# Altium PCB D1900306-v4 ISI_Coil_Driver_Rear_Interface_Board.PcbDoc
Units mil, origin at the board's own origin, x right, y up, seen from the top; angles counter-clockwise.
Board outline 14000 x 2000 mil, 6 copper layers (Top Layer, MidLayer1, InternalPlane1, InternalPlane2, InternalPlane3, Bottom Layer), stack 92.2 mil thick; 51 components, 49 nets, 219 pads, 22 vias.
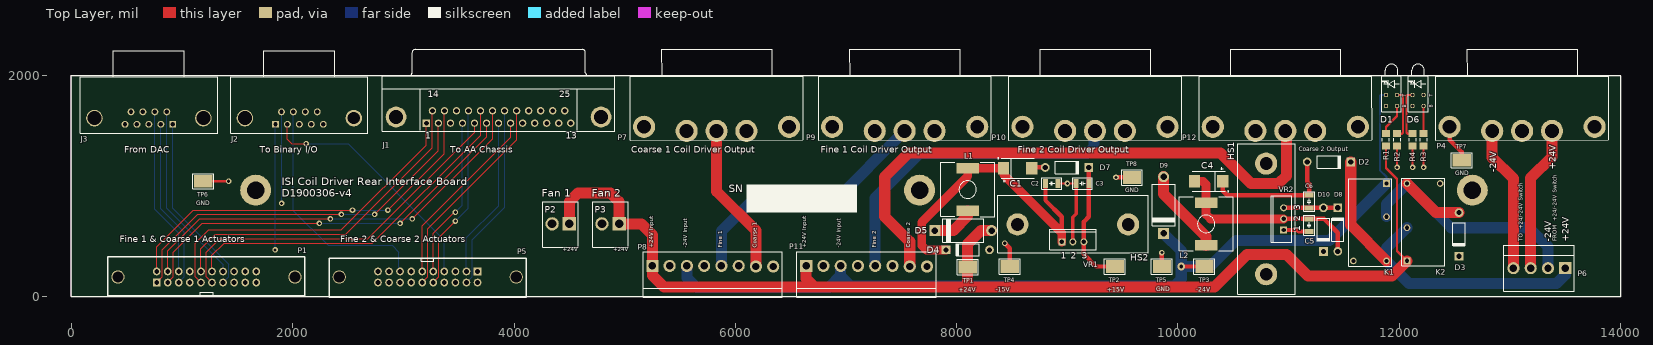
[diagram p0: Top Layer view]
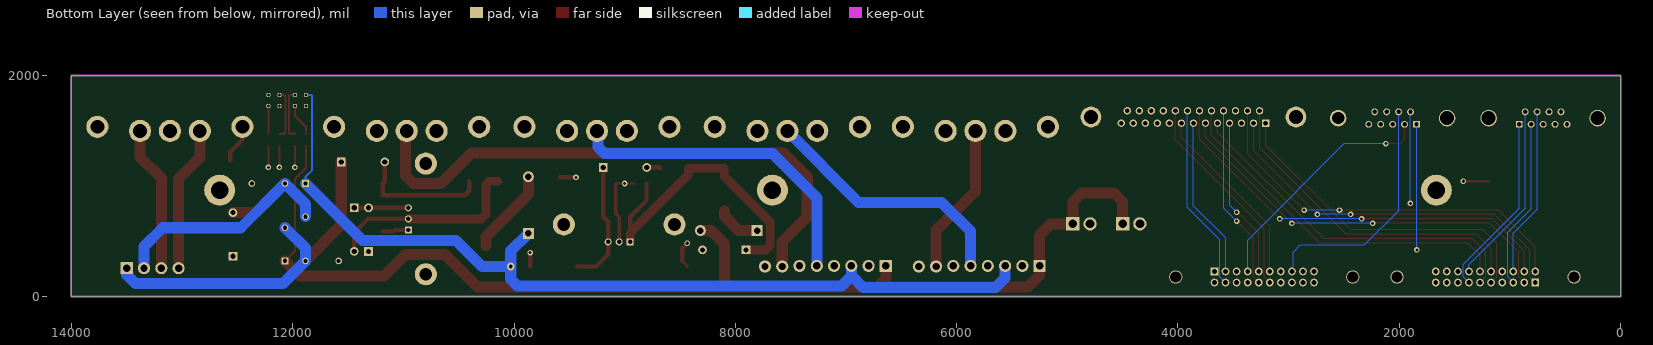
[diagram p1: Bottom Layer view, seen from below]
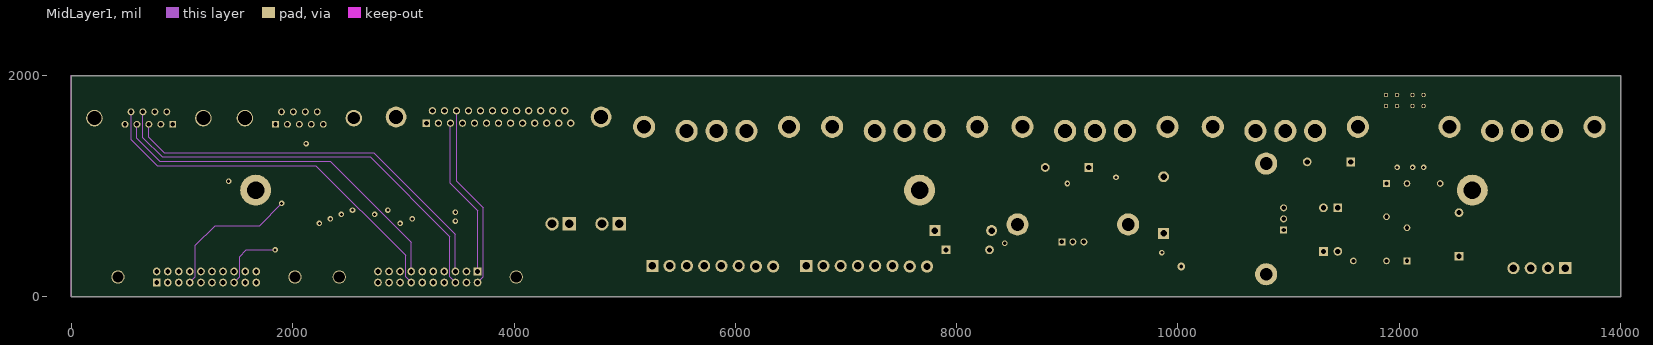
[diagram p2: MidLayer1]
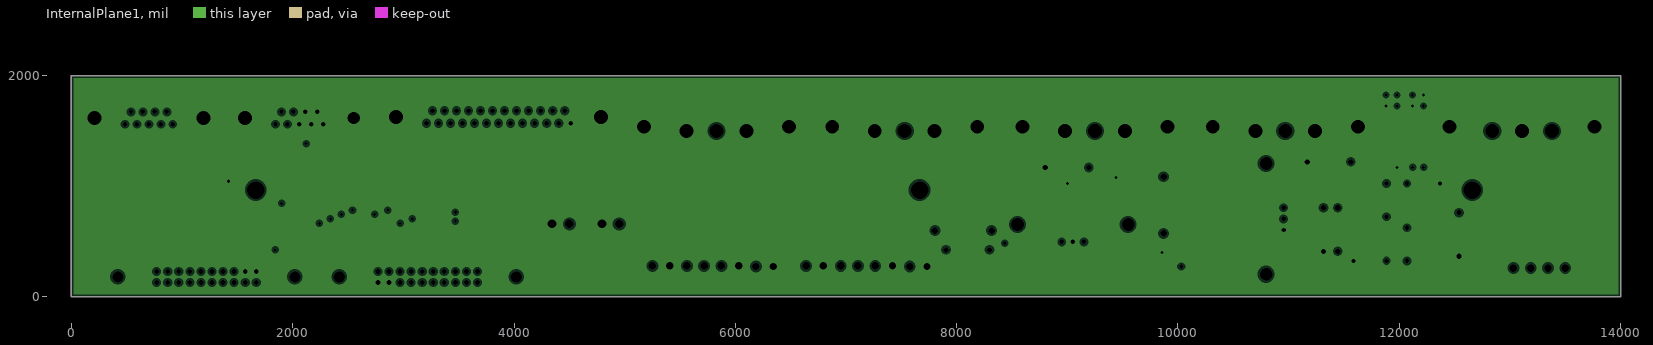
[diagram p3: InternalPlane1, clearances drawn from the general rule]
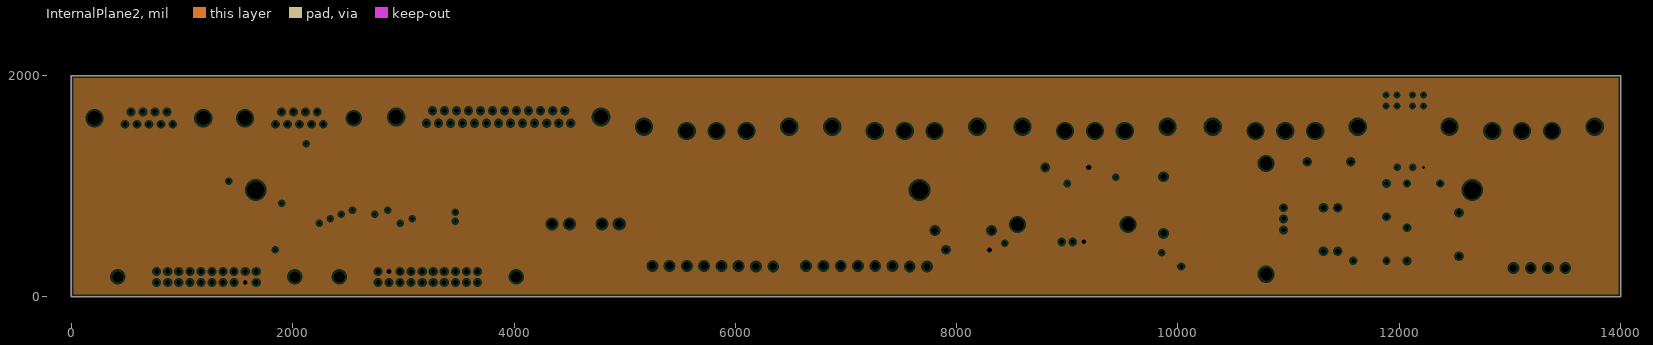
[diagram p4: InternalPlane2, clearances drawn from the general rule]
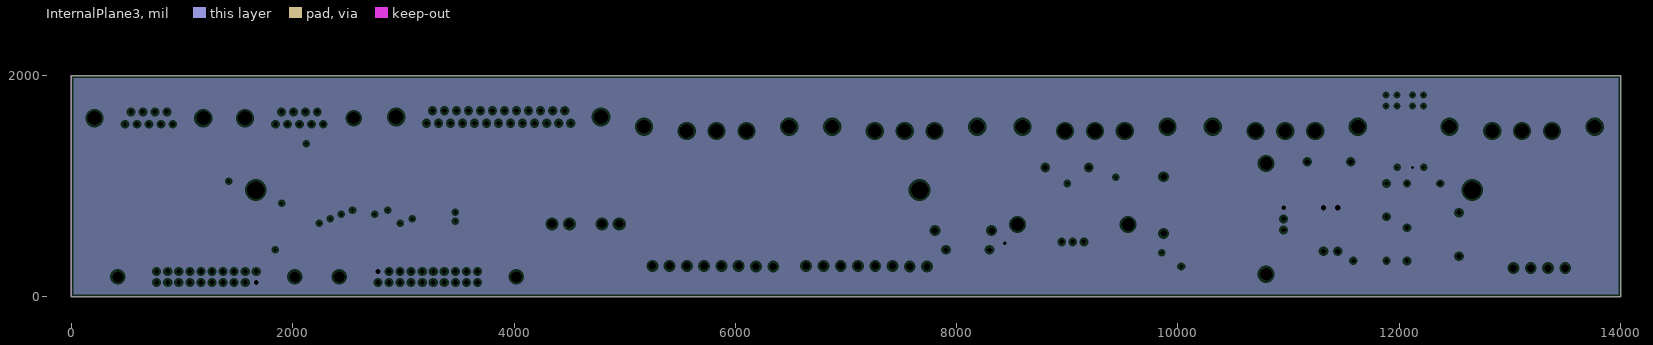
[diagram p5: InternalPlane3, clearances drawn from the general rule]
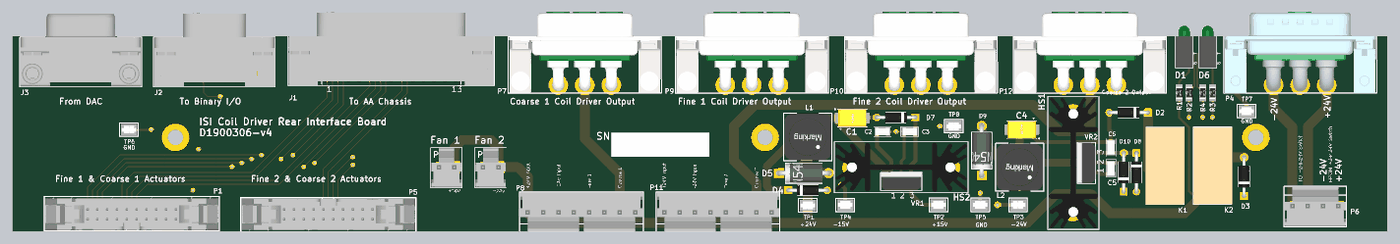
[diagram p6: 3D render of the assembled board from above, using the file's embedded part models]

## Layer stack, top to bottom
Top Solder: solder mask 0.4, Solder Resist, Dk 3.5
Top Layer: signal copper 1.4
Dielectric1: prepreg 9.7, FR-4, Dk 4.2
MidLayer1: signal copper 1.4
Dielectric2: core 27.35, FR-4, Dk 4.2
InternalPlane1: plane copper 1.4, net GND
Dielectric3: prepreg 9.7, FR-4, Dk 4.2
InternalPlane2: plane copper 1.4, net +15
Dielectric4: core 27.35, FR-4, Dk 4.2
InternalPlane3: plane copper 1.4, net -15
Dielectric5: prepreg 9.7, FR-4, Dk 4.2
Bottom Layer: signal copper 1.4
Bottom Solder: solder mask 0.4, Solder Resist, Dk 3.5

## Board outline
0,-5 0,1995 1700,1995 14000,1995 14000,-5 0,-5

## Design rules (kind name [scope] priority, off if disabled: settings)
Clearance [All] p1: gap=10 ignorepadtopadclearanceinfootprint=FALSE except(0: Arc-Hole Track-Hole SMDPad-Hole THPad-Hole Via-Hole Fill-Hole Poly-Hole Region-Hole Text-Hole)
FabricationTestPointUsage TestPointUsage [All] p1: valid=0 allowmultiple=FALSE
FabricationTestpoint Testpoint [All] p1: side=3 testpointundercomponent=TRUE minsize=40 maxsize=100 preferedsize=60 minholesize=0 maxholesize=40 preferedholesize=32 testpointgrid=1 allowsidetop=TRUE allowsidebottom=TRUE usegrid=TRUE gridtolerance=0.01
Height [All] p1: minheight=0 maxheight=4000 prefheight=2000
HoleSize [All] p1: absolutevalues=TRUE maxlimit=300 minlimit=1 maxpercent=80.000 minpercent=20.000
PlaneClearance [All] p1: clearance=20
PlaneConnect [All] p1: planeconnectstyle=Relief reliefexpansion=30 reliefentries=4 reliefconductorwidth=30 reliefairgap=20
PolygonConnect [All] p1: connectstyle=Relief reliefconductorwidth=10 reliefentries=4 polygonreliefangle="90 Angle" airgapwidth=10
RoomDefinition "D1900306-v4 ISI_Coil_Driver_Rear_Interface_Board" [InComponentClass('D1900306-v4 ISI_Coil_Driver_Rear_Interface_Board')] p1: confinementstyle=ConfineIn formatcopy=TRUE lockcomponents=FALSE outline 65,-25 13905,-25 13905,2255 65,2255
RoutingVias [All] p1: holewidth=28 width=50 viastyle="Through Hole" minholewidth=28 minwidth=50 maxholewidth=128 maxwidth=150
SolderMaskExpansion [All] p1: expansion=4 istentingtop=FALSE
Width [All] p1: maxlimit=200 minlimit=5 preferedwidth=20
24 further rules are at their usual default settings.

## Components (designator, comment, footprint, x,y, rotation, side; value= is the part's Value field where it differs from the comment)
C1 "33uF, 50V" T543x 8551.77,1157.91 r180 top
C2 "1uF" "1206 (3216 METRIC) CAP" 8860,1020 r180 top
C3 "0.1uF 50V" "1206 (3216 METRIC) CAP" 9137.09,1020 r180 top
C4 "33uF, 50V" T543x 10277.74,1040 r0 top
C5 "1uF" "1206 (3216 METRIC) CAP" 11185,642.91 r90 top
C6 "0.1uF 50V" "1206 (3216 METRIC) CAP" 11185,857.09 r90 top
D1 "Stacked LED" DUAL_LED 11840,1995 r90 top
D2 "1N4001" DO-41 11365,1215 r0 top
D3 "1N4001" DO-41 12540,560 r270 top
D4 "1N4001" DO-41 8100,420 r180 top
D5 "1N5404" DO-201AD 8060,595 r180 top
D6 "Stacked LED" DUAL_LED 12080,1995 r90 top
D7 "1N4001" DO-41 8997.32,1165 r0 top
D8 "1N4001" DO-41 11445,603.15 r90 top
D9 "1N5404" DO-201AD 9870,825 r270 top
D10 "1N4001" DO-41 11315,603.15 r270 top
HS1 "Heat Sink" "HEAT SINK TO-220" 10797,700 r90 top
HS2 "Heat Sink" "HEAT SINK TO-220" 9050,650 r180 top
J1 "D Connector 25" DSUB1.385-2H25A 3860,1995 r0 top
J2 "D9F 90deg" DB9/F/RA 2060,1555 r0 top
J3 "D9M 90deg" DB9/M/RA 700,1555 r0 top
K1 "Relay-SPST" "PANASONIC RELAY_5A" 11885,1020 r90 top
K2 "Relay-SPST" "PANASONIC RELAY_5A" 12070,320 r270 top
L1 "1.43 uH, 12A, choke" "POWER CHOKE" 8100,965 r0 top
L2 "1.43 uH, 12A, choke" "POWER CHOKE" 10255,655 r0 top
P1 "Header 20" "IDC 20 _VERTICAL" 1220,175 r0 top
P2 "Molex 2 PIN" MOLE_2PIN_0.156 4500,655 r270 top
P3 "Molex 2 PIN" MOLE_2PIN_0.156 4950,655 r270 top
P4 "Conec-3 (MFM)" "CONEC-3 - (+/-24V M/F/M) PWR IN (10.7MM TAB)" 13380,1495 r90 top
P5 "Header 20" "IDC 20 _VERTICAL" 3220,175 r180 top
P6 "Header 4" "4 PIN_MOLEX" 13500,255 r0 top
P7 "Conec-3 (F)" "CONEC-3 - (FFF) PWR OUT (10.7MM TABS)" 6100,1495 r90 top
P8 "8 Pin Molex (0.156\")" "8 PIN_MOLEX(0.156)" 5250,275 r180 top
P9 "Conec-3 (F)" "CONEC-3 - (FFF) PWR OUT (10.7MM TABS)" 7800,1495 r90 top
P10 "Conec-3 (F)" "CONEC-3 - (FFF) PWR OUT (10.7MM TABS)" 9520,1495 r90 top
P11 "8 Pin Molex (0.156\")" "8 PIN_MOLEX(0.156)" 6640,275 r180 top
P12 "Conec-3 (F)" "CONEC-3 - (FFF) PWR OUT (10.7MM TABS)" 11240,1495 r90 top
R1 "1K" 3216[1206] 11880,1415 r90 top
R2 "1K" 3216[1206] 11980,1414.88 r90 top
R3 "1K" 3216[1206] 12220,1415 r90 top
R4 "1K" 3216[1206] 12120,1415 r90 top
TP1 "SMT TP" SMT_TP 8100,265 r90 top
TP2 "SMT TP" SMT_TP 9430,270 r90 top
TP3 "SMT TP" SMT_TP 10240,270 r90 top
TP4 "SMT TP" SMT_TP 8480,270 r270 top
TP5 "SMT TP" SMT_TP 9855,270 r90 top
TP6 "SMT TP" SMT_TP 1192,1040 r90 top
TP7 "SMT TP" SMT_TP 12565,1230 r90 top
TP8 "SMT TP" SMT_TP 9585,1075 r90 top
VR1 "LM340T" TO-220AB 9050,492 r0 top
VR2 "LM7915CT" TO-220AB 10955,700 r90 top

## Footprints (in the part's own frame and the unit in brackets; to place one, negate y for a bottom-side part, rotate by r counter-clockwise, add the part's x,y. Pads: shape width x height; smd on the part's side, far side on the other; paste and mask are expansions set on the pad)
"4 PIN_MOLEX" [mil]
  rect 110x110 hole 67: 1(0,0)
  round 110 hole 67: 2(-156,0) 3(-312,0) 4(-468,0)
  silkscreen extent -554,-210 81,205, body extent -544,-199 74,195, height 581
"8 PIN_MOLEX(0.156)" [mil]
  rect 110x110 hole 67: 1(0,0)
  round 110 hole 67: 2(-156,0) 3(-312,0) 4(-468,0) 5(-624,0) 6(-780,0) 7(-936,5) 8(-1092,5)
  silkscreen extent -1176,-128 84,282, body extent -1167,-121 75,273, height 581
"1206 (3216 METRIC) CAP" [mm] "Chip Capacitor; Body 3.2 x 1.6 mm (LxW typ)"
  rect 1.15x2.1 smd: 1(-1.45,0) 2(1.45,0)
  silkscreen extent -2.29,-1.27 2.29,1.27, body extent -1.8,-0.93 1.8,0.97, height 1.11
3216[1206] [mm] "Chip Resistor; Body 3.2 x 1.6 mm (LxW typ)"
  rect 1.6x1.8 smd: 1(-1.4,0) 2(1.4,0)
  silkscreen extent -0.3,-0.8 0.3,0.8, body extent -1.6,-0.8 1.6,0.8, height 0.55
"CONEC-3 - (+/-24V M/F/M) PWR IN (10.7MM TAB)" [mil] "303W3CPXX56K40X"
  round 200 hole 125: 1(0,0) 2(0,270) 3(0,540) 4(37.4,925) 5(37.4,-386)
  silkscreen extent -83,-510 736,1048, body extent -87,-502 748,1042, height 544
"CONEC-3 - (FFF) PWR OUT (10.7MM TABS)" [mil] "3003W3SXX56K40X"
  round 200 hole 125: 1(0,0) 2(0,270) 3(0,540) 4(37.4,925) 5(37.4,-386)
  silkscreen extent -83,-510 736,1048, body extent -79,-502 748,1042, height 499
DB9/F/RA [mil] "Amphenol part# 617-C009S-AJ120"
  rect 62x62 hole 40: 1(-216,0)
  round 62 hole 40: 2(-108,0) 3(0,0) 4(108,0) 5(216,0) 6(-162,112) 7(-54,112) 8(54,112) 9(162,112)
  round 150 hole 126: 10(-492,56)
  round 150 hole 110: 11(492,56)
  silkscreen extent -620,-80 620,666, body extent -610,-70 610,674, height 495
DB9/M/RA [mil] "Amphenol Part# 617-C009P-AJ120"
  rect 62x62 hole 40: 1(216,0)
  round 62 hole 40: 2(108,0) 3(0,0) 4(-108,0) 5(-216,0) 6(162,112) 7(54,112) 8(-54,112) 9(-162,112)
  round 150 hole 126: 10(492,56) 11(-492,56)
  silkscreen extent -620,-80 620,666, body extent -611,-70 611,662, height 495
DO-41 [mm] "Diode, Axial; Body 5.2 x 2.7 mm (LxDia. max), Lead Dia. 0.86 mm (max)"
  round 2 hole 1.2: 1(-5,0)
  rect 2x2 hole 1.2: 2(5,0)
  silkscreen extent -2.65,-1.42 2.75,1.4, body extent -5.4,-1.36 5.46,1.36, height 2.86
DO-201AD [mm] "Diode Standard 400V 3A Through Hole DO-201AD"
  round 2.5 hole 1.5: 1(-6.5,0)
  rect 2.5x2.5 hole 1.5: 2(6.5,0)
  silkscreen extent -4.75,-2.65 4.75,2.65, body extent -6.95,-2.58 6.95,2.45, height 5.51
DSUB1.385-2H25A [mm] "Connector; D Subminiature; 25 Position; Right Angle; Pitch 1.385 mm"
  rect 1.69x1.69 hole 1.09: 1(-16.566,-10.92)
  round 1.69 hole 1.09: 2(-13.805,-10.92) 3(-11.044,-10.92) 4(-8.283,-10.92) 5(-5.522,-10.92) 6(-2.761,-10.92) 7(0,-10.92) 8(2.761,-10.92) 9(5.522,-10.92) 10(8.283,-10.92) 11(11.044,-10.92) 12(13.805,-10.92) 13(16.566,-10.92) 14(-15.185,-8.08) 15(-12.425,-8.08) 16(-9.663,-8.08) 17(-6.903,-8.08) 18(-4.142,-8.08) 19(-1.38,-8.08) 20(1.38,-8.08) 21(4.142,-8.08) 22(6.903,-8.08) 23(9.663,-8.08) 24(12.425,-8.08) 25(15.185,-8.08)
  round 4.76 hole 3.26: 26(-23.526,-9.5) 27(23.526,-9.5)
  silkscreen extent -26.67,-12.83 26.67,6, body extent -26.54,-12.7 26.54,6.25, height 12.56
DUAL_LED [mil] "Stacked LED GREEN, Digi Key Part # 67-1321-ND"
  round 40 hole 25: 1(-175,-140) 2(-175,-40) 3(-275,-140) 4(-275,-40)
  silkscreen extent -325,-180 104,0, body extent -320,-175 104,-5, height 380
"HEAT SINK TO-220" [mil]
  round 200 hole 115: 1(-500,0) 2(500,0)
  silkscreen extent -680,-265 680,255, body extent -670,-257 670,247, height 2005
"IDC 20 _VERTICAL" [mil]
  round 120 hole 100: 0(-800,0) 0(800,0)
  rect 70x70 hole 43: 1(-450,-50)
  round 70 hole 43: 2(-450,50) 3(-350,-50) 4(-350,50) 5(-250,-50) 6(-250,50) 7(-150,-50) 8(-150,50) 9(-50,-50) 10(-50,50) 11(50,-50) 12(50,50) 13(150,-50) 14(150,50) 15(250,-50) 16(250,50) 17(350,-50) 18(350,50) 19(450,-50) 20(450,50)
  silkscreen extent -891,-170 890,182, body extent -881,-159 879,172, height 1044
MOLE_2PIN_0.156 [mil]
  rect 120x120 hole 79: 1(0,0)
  round 120 hole 79: 2(0,-156)
  silkscreen extent -200,-240 210,80, body extent -193,-231 201,75, height 581
"PANASONIC RELAY_5A" [mil]
  rect 60x60 hole 40: 1(0,0)
  round 60 hole 40: 2(-300,0)
  round 60 hole 36: 3(-700,0) 4(-700,300)
  silkscreen extent -746,-47 44,343, body extent -744,-47 43,347, height 630
"POWER CHOKE" [mm] "PCD1572-ND"
  rect 5.2x2.4 smd: 1(0,-4.9) 2(0,4.9)
  silkscreen extent -6.22,-6.2 6.22,6.22, body extent -6,-6 6,6, height 9.46
SMT_TP [mil] "Surface Mount Test Point"
  rect 115x165 smd: 1(0,0)
  silkscreen extent -69,-94 70,95, body extent -40,-75 40,75, height 91
T543x [mm]
  rect 2.55x2.77 smd: 1(3.22,0) 2(-3.22,0)
  silkscreen extent -3.8,-2.42 4.57,3.18, body extent -3.8,-2.31 3.8,2.29, height 4.31
TO-220AB [mm] "TO, Thru-Hole, Vertical, Heatsink Mounted; 3 In-Line Leads; Pitch 2.54 mm"
  rect 1.6x1.6 hole 1: 1(-2.54,0)
  round 1.6 hole 1: 2(0,0) 3(2.54,0)
  silkscreen extent -5.35,-1.85 5.35,2.85, body extent -5.27,-1.84 5.27,2.86, height 22.56

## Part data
C1 C4: library part T543X, "33µF Molded Tantalum Polymer Capacitor 50V 2917 (7343 Metric) 40mOhm @ 100kHz", Capacitance=33uF, Case/Package=Molded, Case Code (Imperial)=2917, Case Code (Metric)=7343, Dielectric Material=Tantalum, ESR (Equivalent Series Resistance)=40mR, Leakage Current=165uA, Manufacturer=KEMET, Manufacturer Part Number=T543X336M050AHE040, Max Operating Temperature=105°C, Min Operating Temperature=-55°C, Package Quantity=500, Supplier Part Number 1=399-8854-1-ND, Tolerance=20%, Voltage=50V
C2 C5: library part CAP, "1µF ±10% 25V Ceramic Capacitor X7R 1206 (3216 Metric)", Case/Package=1206, Dielectric=X7R, Dielectric Material=Ceramic, Manufacturer=TDK-Lambda, Manufacturer Part Number=C1206C105K3RACTU, Supplier Part Number 1=399-1255-1-ND, Tolerance=10%, Voltage Rating (DC)=25V
C3 C6: "0.1µF ±5% 50V Ceramic Capacitor X7R 1206 (3216 Metric)", Capacitance=100nF, Case/Package=1206, Case Code (Metric)=3216, Dielectric=X7R, Dielectric Material=Ceramic, Manufacturer=KEMET, Manufacturer Part Number=C1206C104J5RACTU, Max Operating Temperature=125°C, Min Operating Temperature=-55°C, Package Quantity=1, Supplier Part Number 1=399-1250-1-ND, Tolerance=5%, Voltage=50V
D1 D6: library part "Dual Stacked LED", "Dual Green LED", Color=Green, Forward Current=25mA, Forward Voltage=2.2V, Manufacturer=Lumex, Manufacturer Part Number=SSF-LXH240GGD, Package Quantity=1000, Supplier Part Number 1=67-1321-ND
D2 D3 D4 D7 D8 D10: library part "Diode 1N4001", "1 Amp General Purpose Rectifier", Average Rectified Current=1A, Capacitance=8pF, Forward Voltage=1V, Manufacturer=Diodes, Manufacturer Part Number=1N4001G-T, Max Operating Temperature=175°C, Max Repetitive Reverse Voltage (Vrrm)=50V, Max Surge Current=30A, Min Operating Temperature=-65°C, Package Quantity=5000, Peak Reverse Current=5uA, Supplier Part Number 1=1N4001GDICT-ND
D5 D9: library part "Diode 1N5404", "Diode Standard 400V 3A Through Hole DO-201AD", Average Rectified Current=3A, Capacitance=30pF, Forward Voltage=1.2V, Manufacturer="Vishay Semiconductors", Manufacturer Part Number=1N5404-E3/54, Max Forward Surge Current (Ifsm)=200A, Max Operating Temperature=150°C, Max Repetitive Reverse Voltage (Vrrm)=400V, Min Operating Temperature=-50°C, Package Quantity=1, Peak Reverse Current=5uA, Supplier Part Number 1=1N5404-E3/54GICT-ND
HS1 HS2: "Heat Sink TO-220 Aluminum 8.0W @ 80°C Board Level, Vertical", Case/Package=TO-220, Color=Black, Manufacturer=Ohmite, Manufacturer Part Number=EA-T220-38E, Natural Thermal Resistance=10.4°C/W, Package Quantity=10, Supplier Part Number 1=EA-T220-38E-ND, Thermal Resistance @ Forced Air Flow (100 LFM)=4°C/W
J1: "25 Position D-Sub Receptacle, Female Sockets Connector", Case/Package=Metal, Color=Black, Current Rating=6A, Flammability Rating="UL94 V-0", Manufacturer="TE Connectivity", Manufacturer Part Number=57478464, Max Operating Temperature=105°C, Min Operating Temperature=-55°C, PackageDocument=U, Package Quantity=65, Supplier Part Number 1=A32126-ND, Voltage Rating=125V
J2: library part DB9/F/RA, "Receptacle Assembly, 9 Position, Right Angle", Manufacturer="AMP - TE CONNECTIVITY", Manufacturer Part Number=5747844-4, Supplier Part Number 1=A32117-ND
J3: library part DB9/M/RA, "9 Position D-Sub Plug, Male Pins Connector", Case/Package=Metal, Color=Black, Contact Current Rating=6A, Flammability Rating="UL94 V-0", Manufacturer="TE Connectivity", Manufacturer Part Number=5747840-3, Max Operating Temperature=221°C, Min Operating Temperature=-67°C, Package Quantity=130, Supplier Part Number 1=A32091-ND, Voltage Rating=125V
K1 K2: "Single-Pole Single-Throw Relay", Coil Current=8.3mA, Coil Power=200mW, Coil Resistance=2.88kR, Coil Voltage (DC)=24V, Contact Current Rating=5A, Manufacturer=Panasonic, Manufacturer Part Number=JQ1A-24V-F, Max Operating Temperature=70°C, Max Voltage Rating (AC)=250V, Max Voltage Rating (DC)=110V, Min Operating Temperature=-40°C, Package Quantity=100, Supplier Part Number 1=255-2069-ND
L1 L2: library part INDUCTOR, "1mH Shielded  Inductor 550mA 1.82Ohm Max Nonstandard", Case/Package=Nonstandard, Current Rating=550mA, DC Resistance (DCR)=1.82R, Inductance=1mH, Manufacturer=Sumida, Manufacturer Part Number=CDRH127NP-102MC, Max Operating Temperature=100°C, Min Operating Temperature=-40°C, Package Quantity=500, Supplier Part Number 1=308-2293-1-ND, Test Frequency=1kHz, Tolerance=20%
P1 P5: "Header, 20-Pin", Color=Grey, Current Rating=1A, Flammability Rating="UL94 V-0", Insulation Resistance=100GR, Manufacturer="Amphenol FCI", Manufacturer Part Number=71918-120LF, Max Operating Temperature=125°C, Max Voltage Rating (AC)=1.5kV, Min Operating Temperature=-65°C, Package Quantity=11, Supplier Part Number 1=609-1755-ND
P2 P3: library part "Header 2H (3.96mm)", "Connector Header Through Hole 2 position 0.156\" (3.96mm)", Color=Natural, Contact Resistance=6mR, Current Rating=7A, Flammability Rating="UL94 V-0", Insulation Resistance=50GR, Manufacturer=Molex, Manufacturer Part Number=26-61-4020, Max Operating Temperature=75°C, Max Voltage Rating (AC)=250V, Min Operating Temperature=0°C, Package Quantity=1400, Supplier Part Number 1=WM5224-ND
P4: library part "+/-24 Conec-3 (MFM) (10.7mm Tabs)", "3 (Power) Position D-Sub, Combo Plug, 2 Male Pins, 1 Female Pin Connector (10.7mm Tabs) / Connec PN 303W3CPXX56K40X", Manufacturer Part Number=303W3CPXX56K40X
P6: "Header, 4-Pin", Color=Natural, Contact Resistance=6mR, Current Rating=7A, Flammability Rating="UL94 V-0", Insulation Resistance=50GR, Manufacturer=Molex, Manufacturer Part Number=26-60-4040, Max Operating Temperature=75°C, Min Operating Temperature=0°C, Package Quantity=600, Supplier Part Number 1=WM4622-ND, Voltage Rating=250V
P7 P9 P10 P12: library part "Conec-3 (FFF) (10.7mm Tabs)", "D-Sub Mixed Contact Connectors 3W3 M R/A .370 20 AMP POWER", Manufacturer Part Number=303W3CPXX56K40X
P8 P11: library part "Header 8", "Connector Header Through Hole 8 position 0.156\" (3.96mm)", Color=Natural, Contact Resistance=6mR, Manufacturer=Molex, Manufacturer Part Number=26-60-4080, Max Operating Temperature=75°C, Max Voltage Rating (AC)=250V, Min Operating Temperature=0°C, Supplier Part Number 1=WM4626-ND
R1 R2 R3 R4: library part "Res Semi", "1 kOhms ±0.5% 0.25W, 1/4W Chip Resistor 1206 (3216 Metric)  Thin Film", Case/Package=1206, Case Code (Metric)=3216, Manufacturer=Yageo, Manufacturer Part Number=RT1206DRE071KL, Max Operating Temperature=155°C, Max Power Dissipation=250mW, Min Operating Temperature=-55°C, Resistance=1kR, Supplier Part Number 1=311-2972-1-ND, Temperature Coefficient=50ppm/°C, Tolerance=0.5%, Voltage Rating (DC)=200V
TP1 TP2 TP3 TP4 TP5 TP6 TP7 TP8: "PC Test Point, Miniature Phosphor Bronze, Silver Plating Surface Mount Mounting Type", Manufacturer="Keystone Electronics", Manufacturer Part Number=5019, Package Quantity=1, Supplier Part Number 1=36-5019CT-ND
VR1: "Linear Voltage Regulator IC Positive Fixed 1 Output  1.5A TO-220-3", Case/Package=TO-220, Dropout Voltage=2V, Manufacturer="TI National Semiconductor", Manufacturer Part Number=LM340T-15/NOPB, Max Input Voltage=35V, Max Operating Temperature=125°C, Max Output Current=1A, Max Output Voltage=15V, Max Supply Voltage=30V, Min Input Voltage=17.7V, Min Operating Temperature=0°C, Min Supply Voltage=17.5V, Output Voltage Accuracy=2%, Power Supply Rejection Ratio (PSRR)=80dB, Quiescent Current=8mA, Supplier Part Number 1=LM340T-15/NOPB-ND, Tolerance=5%
VR2: "Linear Voltage Regulator IC Negative Fixed 1 Output  1.5A TO-220-3", Case/Package=TO-220, Dropout Voltage=1.1V, Manufacturer="TI National Semiconductor", Manufacturer Part Number=LM7915CT/NOPB, Max Input Voltage=-23V, Max Operating Temperature=125°C, Max Output Current=1.5A, Max Output Voltage=-15.6V, Min Input Voltage=-17.5V, Min Operating Temperature=0°C, Min Output Voltage=-14.4V, Nominal Output Voltage=-15V, Output Voltage Accuracy=4%, Power Supply Rejection Ratio (PSRR)=70dB, Quiescent Current=3mA, Supplier Part Number 1=LM7915CT/NOPB-ND, Tolerance=5%

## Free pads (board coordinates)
  round 280 hole 157.48: 1(1665,960) 1(7665,960) 1(12660,960)

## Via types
v1: diameter 50, hole 28, Top Layer to Bottom Layer, 21 vias
v2: diameter 70, hole 35, Top Layer to Bottom Layer, 1 vias

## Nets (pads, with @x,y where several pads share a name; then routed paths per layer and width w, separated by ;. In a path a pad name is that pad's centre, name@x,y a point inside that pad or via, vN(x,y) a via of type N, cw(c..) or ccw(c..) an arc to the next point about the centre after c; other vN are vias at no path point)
+15: C3.1 D4.1 D7.2 P1.17 P5.17 R3.1 TP2.1 VR1.3 | length 1323.7
  Top Layer w20: v1(12220,1165) R3.1
  Top Layer w40: D7.2 C3.1 9194.17,719.17 9150,675 VR1.3 9150,380 9260,270 TP2.1
+24RAW: D2.2 K1.3 K2.2 P6.1 | length 3198.5
  Top Layer w100: D2.2 11561.85,643.15 K1.3
  Bottom Layer w100: K2.2 11885,435 K1.3 12090,115 13420,115 13500,195 P6.1
+24V_Input: D5.1 K2.1 P2.1 P3.1 P8.1 P11.1 R1.1 TP1.1 | length 10740.3
  Top Layer w20: R1.1 11880,1160 11980,1060 11980,410 K2.1
  Top Layer w100: P2.1 4500,855 4580,935 4870,935 4950,855 P3.1 5150,655 5250,555 P8.1 5250,190 5355,85 6715,85 ; P11.1 6640,160 6715,85 ; D5.1 8220,595 8100,475 TP1.1 8100,85 ; K2.1 11935,185 11175,185 10980,380 10625,380 10330,85 8405,85 8100,85 ; 6715,85 8100,85
-15: C6.1 D8.2 D10.1 P1.19 P5.19 R4.1 TP4.1 VR2.3 | length 941.3
  Top Layer w20: TP4.1@8435,265 8430,270 TP4.1@8480,320 ; v1(12120,1165) R4.1
  Top Layer w40: v1(8435,480) 8480,435 TP4.1@8480,320 ; VR2.3 C6.1 D10.1 D8.2
-24RAW: D3.1 K1.2 K2.3 P6.2 | length 2661.3
  Top Layer w100: K2.3 12333.15,756.85 D3.1
  Bottom Layer w100: K1.2 11885,835 K2.3 12470,620 13175,620 13344,451 P6.2
-24V_Input: D1.2 D9.2 K1.1 P8.3 P11.3 TP3.1 | length 8539.1
  Top Layer w40: v2(10030,270) TP3.1
  Bottom Layer w20: D1.2 11835,1820 11825,1810 11825,1140 11885,1080 K1.1
  Bottom Layer w100: P8.3 5562,168 5650,80 6845,80 6952,187 ; P11.3 6952,187 ; D9.2 10030,409.09 v2(10030,270) ; K1.1 11370.67,505.67 10525.67,505.67 10290,270 v2(10030,270) ; 6952,187 6952,183 7040,95 9970,95 10030,155 v2(10030,270)
"Coarse 1": P7.2 P8.7 | length 1372.5
  Top Layer w100: P7.2 5830,950 6186,594 P8.7
"Coarse 2": P11.7 P12.2 | length 5170.6
  Top Layer w100: P11.7 7576,494 7350,720 7350,1080 7565,1295 10385,1295 10660,1020 10910,1020 10980,1090 P12.2@10980,1495
"Fine 1": P8.5 P9.2 | length 2345.3
  Bottom Layer w100: P8.5 5874,589 6135,850 6885,850 P9.2
"Fine 2": P10.2 P11.5 | length 2932.2
  Bottom Layer w100: P11.5 7264,888.37 7665.63,1290 9184.29,1290 9242.87,1348.58 9242.87,1487.87 P10.2
GND: C1.2 C2.1 C3.2 C4.1 C5.1 C6.2 D1.4 D2.1 D3.2 D6.1 D6.4 D7.1 D10.2 J1.13 J1.26 J1.27 J2.3 J2.4 J2.5 J2.8 J2.9 J2.10 J2.11 J3.10 J3.11 K1.4 K2.4 P1.18 P1.20 P2.2 P3.2 P4.2 P4.4 P4.5 P5.18 P5.20 P7.1 P7.3 P7.4 P7.5 P8.2 P8.6 P8.8 P9.1 P9.3 P9.4 P9.5 P10.1 P10.3 P10.4 P10.5 P11.2 P11.6 P11.8 P12.1 P12.3 P12.4 P12.5 R2.1 TP5.1 TP6.1 TP7.1 TP8.1 VR1.2 VR2.1 | length 3294.7
  Top Layer w20: TP6.1 v1(1420,1040) ; C2.1 v1(9000,1020) C3.2 ; v1(11980,1165) R2.1
  Top Layer w30: VR1.2 9050,715 9080,745 C3.2
  Top Layer w40: C1.2 8685.63,1165 D7.1 ; v1(9440,1075) TP8.1 ; TP5.1 v1(9855,395) ; C4.1 10404.51,955.49 10445.83,914.17 C6.2 11185,1020 11168.15,1036.85 D2.1 ; VR2.1 11075.83,600 11090,585.83 C5.1 ; P4.4 12455,1415 12565,1305 TP7.1
NetC1_1: C1.1 C2.2 D4.2 L1.2 VR1.1 | length 2818.8
  Top Layer w40: C2.2 8802.91,867.09 8950,720 8950,575
  Top Layer w80: D4.2 7725,420 7685,460 7685,670 8100,1085 L1.2 C1.1 8425,1100 8950,575 VR1.1
NetC4_2: C4.2 C5.2 D8.1 L2.2 VR2.2 | length 1800.6
  Top Layer w40: VR2.2 C5.2 11320,700 11445,575 D8.1
  Top Layer w80: C4.2 10225,1040 10255,1010 L2.2 ; L2.2@10255,835 10255,740 10295,700 VR2.2
NetD1_1: D1.1 R2.2 | length 448.2
  Top Layer w20: R2.2@11980,1470.12 12025.12,1470.12 12035,1480 12035,1810 12025,1820 D1.1
NetD1_3: D1.3 R1.2 | length 291.3
  Top Layer w20: R1.2 11880,1530 11980,1630 D1.3
NetD5_2: D5.2 L1.1 | length 396.8
  Top Layer w100: D5.2 7970,595 8100,725 L1.1
NetD6_2: D6.2 R4.2 | length 448.2
  Top Layer w20: R4.2 12074.88,1470.12 12065,1480 12065,1810 12075,1820 D6.2
NetD6_3: D6.3 R3.2 | length 249.9
  Top Layer w20: R3.2 D6.3
NetD9_1: D9.1 L2.1 | length 778.3
  Top Layer w100: D9.1 9870,925 10255,540 L2.1
NetJ1_1: J1.1 P1.9 | length 3028.5
  Top Layer w10: P1.9 1120,175 1120,480 1220,580 1240,600 2440,600 3207.8,1367.8 J1.1
NetJ1_2: J1.2 P1.1 | length 3432.1
  Top Layer w10: P1.1 820,175 820,420 1140,740 v1(2440,740) ; v1(2740,740) 3316.5,1316.5 J1.2
  Bottom Layer w10: v1(2440,740) v1(2740,740)
NetJ1_3: J1.3 P5.1 | length 1441.5
  MidLayer1 w10: J1.3 3425.2,1020 3670,775.2 P5.1
NetJ1_4: J1.4 P5.9 | length 1455.2
  Top Layer w10: P5.9 3270,570 3460,760 v1(3470,760)
  Bottom Layer w10: v1(3470,760) 3533.9,823.9 J1.4
NetJ1_5: J1.5 P1.11 | length 3249.2
  Top Layer w10: P1.11 1220,175 1220,400 1340,520 2680,520 3642.6,1482.6 J1.5
NetJ1_6: J1.6 P1.3 | length 3682.1
  Top Layer w10: P1.3 920,175 920,400 1180,660 v1(2240,660) ; v1(2970,660) 3751.3,1441.3 J1.6
  Bottom Layer w10: v1(2240,660) v1(2970,660)
NetJ1_7: J1.7 P5.3 | length 1460.2
  Bottom Layer w10: P5.3 3570,530 3860,820 J1.7
NetJ1_8: J1.8 P5.11 | length 1670.9
  Top Layer w10: P5.11 3170,640 3968.7,1438.7 J1.8
NetJ1_14: J1.14 P1.10 | length 3009.7
  Top Layer w10: P1.10 1170,430 1300,560 2480,560 3262.15,1342.15 J1.14
NetJ1_15: J1.15 P1.2 | length 3560.2
  Top Layer w10: P1.2 770,450 1100,780 v1(2540,780) ; v1(2860,780) 3370.85,1290.85 J1.15
  Bottom Layer w10: v1(2540,780) v1(2860,780)
NetJ1_16: J1.16 P5.2 | length 1672.2
  MidLayer1 w10: J1.16 3480,1676.44 3480,1040 3720,800 3720,175 P5.2
NetJ1_17: J1.17 P5.10 | length 1683.7
  Top Layer w10: P5.10 3320,175 3320,530 v1(3470,680)
  Bottom Layer w10: v1(3470,680) 3588.25,798.25 J1.17
NetJ1_18: J1.18 P1.12 | length 3242.1
  Top Layer w10: P1.12 1270,370 1380,480 2720,480 3696.95,1456.95 J1.18
NetJ1_19: J1.19 P1.4 | length 3792.6
  Top Layer w10: P1.4 870,410 1160,700 v1(2340,700) ; v1(3080,700) 3805.65,1425.65 J1.19
  Bottom Layer w10: v1(2340,700) v1(3080,700)
NetJ1_20: J1.20 P5.4 | length 1694.5
  Bottom Layer w10: P5.4 3620,175 3620,510 3914.35,804.35 J1.20
NetJ1_21: J1.21 P5.12 | length 1905.2
  Top Layer w10: P5.12 3220,175 3220,610 4023.05,1413.05 J1.21
NetJ2_1: J2.1 P1.15 | length 1737.2
  MidLayer1 w10: P1.15 1520,175 1520,360 1580,420 v1(1840,420)
  Bottom Layer w10: v1(1840,420) 1840,1551 J2.1
NetJ2_2: J2.2 P5.7 | length 2215.6
  Top Layer w10: J2.2 1952,1420 1992,1380 v1(2120,1380)
  Bottom Layer w10: v1(2120,1380) 2500,1380 3370.85,509.15 3370.85,225.85 P5.7
NetJ2_6: J2.6 P1.7 | length 2120.9
  MidLayer1 w10: P1.7 1120,175 1120,460 1300,640 1700,640 v1(1900,840)
  Bottom Layer w10: J2.6 1899,1666 1899,841 v1(1900,840)
NetJ2_7: J2.7 P5.15 | length 2180.2
  Bottom Layer w10: J2.7 2006,774 2320,460 2898.52,460 2958.52,400 2958.52,236.48 P5.15
NetJ3_1: J3.1 P1.13 | length 1659.5
  Bottom Layer w10: J3.1 916,794 1420,290 1420,175 P1.13
NetJ3_2: J3.2 P1.5 | length 1538.5
  Bottom Layer w10: J3.2 808,792 1020,580 1020,175 P1.5
NetJ3_3: J3.3 P5.5 | length 3584.5
  MidLayer1 w10: J3.3 700,1440 840,1300 2730,1300 3470,560 P5.5
NetJ3_4: J3.4 P5.13 | length 3258.5
  MidLayer1 w10: J3.4 592,1428 800,1220 2340,1220 3070,490 P5.13
NetJ3_6: J3.6 P1.14 | length 1652.4
  Bottom Layer w10: J3.6 862,794 1370,286 P1.14
NetJ3_7: J3.7 P1.6 | length 1531.5
  Bottom Layer w10: J3.7 754,786 970,570 P1.6
NetJ3_8: J3.8 P5.6 | length 3813
  MidLayer1 w10: J3.8 646,1434 820,1260 2700,1260 3420,540 3420,175 P5.6
NetJ3_9: J3.9 P5.14 | length 3432
  MidLayer1 w10: J3.9 540,1665 540,1414 774,1180 2210,1180 3020,370 3020,175 P5.14
NetP4_1: P4.1 P6.3 | length 1333.7
  Top Layer w100: P6.3 13188,1068 13380,1260 P4.1 ; P4.1@13390,1485 P4.1@13400,1495
NetP4_3: P4.3 P6.4 | length 1319.5
  Top Layer w100: P4.3 12840,1255 13032,1063 P6.4
pads on no net: HS1.1 HS1.2 HS2.1 HS2.2 J1.9 J1.10 J1.11 J1.12 J1.22 J1.23 J1.24 J1.25 J3.5 P1.0 P1.8 P1.16 P5.0 P5.8 P5.16 P8.4 P11.4

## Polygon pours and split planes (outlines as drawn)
GND on InternalPlane1 (split plane): 13979.9,15.1 20.1,15.1 20.1,1974.9 13979.9,1974.9
+15 on InternalPlane2 (split plane): 13979.9,15.1 20.1,15.1 20.1,1974.9 13979.9,1974.9
-15 on InternalPlane3 (split plane): 13979.9,15.1 20.1,15.1 20.1,1974.9 13979.9,1974.9

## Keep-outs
Keep-Out Layer:
  lines w10: 0,0 0,2000 7500,2000 14000,2000 14000,1550 14000,0 12850,0 900,0 0,0

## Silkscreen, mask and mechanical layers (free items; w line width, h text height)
Top Overlay:
  rectangle: 6100,760 7100,1010
  lines w5: 0,0 0,2000 14000,2000 14000,0 0,0
  text "Coarse 2 Output" at 11090,1310 h40
  text "From DAC" at 475,1300 h60
  text "To Binary I/O" at 1700,1300 h60
  text "To AA Chassis" at 3425,1300 h60
  text "Coarse 1 Coil Driver Output" at 5060,1300 h60
  text "Fine 1 Coil Driver Output" at 6770,1300 h60
  text "Fine 2 Coil Driver Output" at 8550,1300 h60
  text "+24V" at 13415,1145 h60 r90
  text "-24V" at 12875,1120 h60 r90
  text "GND" at 12505,1095 h40
  text "SN" at 5940,940 h70
  text "GND" at 9525,940.49 h40
  text "ISI Coil Driver Rear Interface Board / D1900306-v4" at 1900,900 h70
  text "Fan 1" at 4250,900 h70
  text "Fan 2" at 4700,900 h70
  text "GND" at 1130,825 h40
  text "TO  +24/-24V Switch" at 13130,500 h60 r90
  text "FROM  +24/-24V Switch" at 13435,500 h60 r90
  text "-24V" at 13375,495 h60 r90
  text "+24V" at 13530,495 h60 r90
  text "Fine 1 & Coarse 1 Actuators" at 435,490 h60
  text "Fine 2 & Coarse 2 Actuators" at 2430,490 h60
  text "+24V Input" at 5270,440 h60 r90
  text "-24V Input" at 5580,440 h60 r90
  text "Fine 1" at 5895,440 h60 r90
  text "Coarse 1" at 6205,440 h60 r90
  text "+24V Input" at 6655,440 h60 r90
  text "-24V Input" at 6965,440 h60 r90
  text "Fine 2" at 7285,440 h60 r90
  text "Coarse 2" at 7595,440 h60 r90
  text "+24V" at 4440,395 h60
  text "+24V" at 4895,395 h60
  text "GND" at 9802,47 h40
  text "+24V" at 8020,40 h40
  text "-15V" at 8355,40 h40
  text "+15V" at 9360,40 h40
  text "-24V" at 10165,40 h40
Mechanical 1:
  lines w5: 0,0 14000,0 14000,2000 0,2000 0,0

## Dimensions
14000,0 to 0,0 on Mechanical 1
14000,2000 to 14000,0 on Mechanical 1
